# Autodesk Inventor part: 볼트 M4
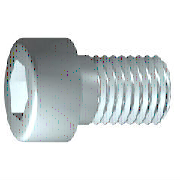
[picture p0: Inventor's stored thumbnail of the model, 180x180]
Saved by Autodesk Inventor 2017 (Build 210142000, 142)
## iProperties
IsCustomPart: 1
Created: 2012-02
Part Number: 볼트 M4
Material: 강철, 연강
Description: 6각머리 태핑 나사
Document SubType Name: Modeling
Standard: KS B 1003
Designer: test
Standards Organization: KS
Language: ko-KR
Size Designation: M 4 x 10
Categories: <MemberInstance><Categories><Category DisplayName="조임쇠" InternalName="e4da775c-781d-43d5-af7c-5136215cf5a6" Mnemonic="FSTN"><Category DisplayName="볼트" InternalN
Density: 1 g/cm^3
Appearance: 강철
Author: test
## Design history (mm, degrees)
sketch "스케치1"
  geometry: L1 (-1, 0)-(10, 0); L2 (10, 0)-(10, 2); L3 (10, 2)-(1.75, 2); L4 (1.75, 2)-(1.32, 2); L5 (1.32, 2)-(0, 2); L6 (0, 2)-(0, 3.5); L7 (0, 3.5)-(-4, 3.5); L8 (-4, 3.5)-(-4, 1.732); L9 (-4, 1.732)-(-2, 1.732); L10 (-2, 1.732)-(-1, 0); L11 (-6.8, 0)-(12.8, 0) reference; L12 (0, -0.7)-(0, 4.2) reference; L13 (1.75, 2)-(0, 2)
  constraints: 22 end point, 6 parallel, 2 collinear, 2 perpendicular, 1 horizontal, 1 point on line
  dimensions: "d1" = 8.25 distance from line of L3.end L2 (= GEL); "d2" = 0.42952 distance of L4.end L3.end (computed from GAL); "d3" = 4 distance between parallel lines of L8 L6 (= KOH); "d4" = 2 distance of L8.end L9.end (= INTI); "d5" = 60 deg angle of L10 L1; "d6" = 4 diameter of L3 L1 (= GD); "d7" = 4 diameter of L5 L1 (= BDM); "d8" = 3.4641 diameter of L9 L1 (= 1.1547 x SW); "d9" = 7 diameter of L7 L1 (= KOD); "d26" = 10 distance between parallel lines of L12 L2 (= NLG)
revolve "본체" sketch "스케치1" stored, may be unused: angle "d10" = 90 deg
sketch "스케치2"
  geometry: L1 (0, -4.9)-(0, 4.9) reference; L2 (-4.9, 0)-(4.9, 0) reference; L3 (1.732, 0)-(0.866, -1.5); L4 (0.866, -1.5)-(-0.866, -1.5); L5 (-0.866, -1.5)-(-1.732, 0); L6 (-1.732, 0)-(-0.866, 1.5); L7 (-0.866, 1.5)-(0.866, 1.5); L8 (0.866, 1.5)-(1.732, 0); 2 further points
  constraints: 12 end point, 1 coincident, 1 horizontal alignment, 1 point on line, 12 other
extrude "슬롯" join sketch "스케치2" stored distance "d11" = 10; taper "d12" = 0 deg
workplane "Work Plane1"
fillet "Fillet2" dims "d30" = 0.1 (= R)
body "Solid1"
fillet "모깎기1" dims "d17" = 0.4 (= RR)
feature "스레드" dims "d13" = 8.25 (= GEL), "d14" = 0
chamfer "모따기1" distance "d15" = 0.42941 (= -0.5 x SPD + 0.5 x GD); stored, may be unused: second distance "d16" = 0.42941 (= GUL), angle "d27" = 45 deg
other parameters: "GD" = 4 (= NND) [user parameter; used in 2 equation terms], "NLG" = 10 [user parameter; used in 1 equation term], "GEL" = 8.25 [user parameter; used in 2 equation terms], "KOD" = 7 [user parameter; used in 1 equation term], "KOH" = 4 [user parameter; used in 1 equation term], "INTI" = 2 [user parameter; used in 1 equation term], "GAL" = 0.42941 (= 0.61345 x PTC) [user parameter; used in 1 equation term], "GUL" = 0.42941 (= 0.61345 x PTC) [user parameter; used in 1 equation term], "BDM" = 4 (= NND) [user parameter; used in 1 equation term], "SW" = 3 [user parameter; used in 2 equation terms], "RR" = 0.4 [user parameter; used in 1 equation term], "SPD" = 3.14117 (= NND - 1.2269 x PTC) [user parameter; used in 1 equation term], "d19" = 0, "d28" = 0, "d29" = 0, "R" = 0.1 [user parameter; used in 1 equation term], "PHH" = 0.2 [user parameter], "GD1" = 3.14117 (= THREADDIA - 1.2269 x PTC) [user parameter], "THREADDIA" = 4 [user parameter; used in 1 equation term], "FAWI" = 45 deg [user parameter], "TPU" = 14.28571 (computed from PTC) [user parameter], "PTC" = 0.7 [user parameter; used in 5 equation terms], "NND" = 4 [user parameter; used in 3 equation terms], "TOA" = 30 deg [user parameter], "E0" = 3.465 (= 1.155 x SW) [user parameter]
